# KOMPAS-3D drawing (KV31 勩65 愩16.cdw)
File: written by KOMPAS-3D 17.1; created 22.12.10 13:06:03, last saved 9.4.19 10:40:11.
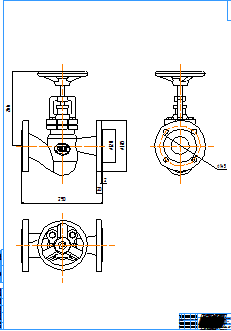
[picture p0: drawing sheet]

Title block, sheet 1: name: KV31 Ду65 Ру16; material: Внимание! Данный продукт является объектом авторского права ООО «Торговый Дом АДЛ». / Запрещается изменение, копирование, распространение / (в том числе путем копирования на другие сайты и ресурсы в Интернете) / или любое иное использование информации и объектов без предварительного / согласия правообладателя (ООО «Торговый Дом АДЛ»).; mass: 21; scale: 1:1; sheets: 1; organisation: ООО "Торговый дом АДЛ"; sheet format: A0; stored path: \\adlc.lan\data\АДЛ_ПКД\3D-модели\ADL production\Вентили ГРАНВЕНТ\KV31\KOMPAS 2D\KV31 Ду65.cdw

Views: Спереди 1, Проекционный вид 2, Проекционный вид 3
Dimensions and other numbers on the sheet: 120; 185; 2; 20; 290; 145; 266; 1:1; 1; 21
